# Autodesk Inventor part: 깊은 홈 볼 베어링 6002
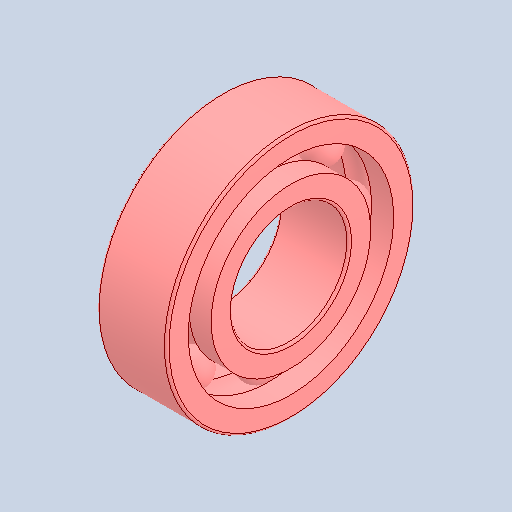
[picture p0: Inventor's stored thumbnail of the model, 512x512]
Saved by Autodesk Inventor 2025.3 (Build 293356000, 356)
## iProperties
Created: 2025-10
Part Number: 깊은 홈 볼 베어링 6002
Material: 강철, 연강
Description: 깊은 그루브 볼 베어링
Document SubType Name: Modeling
Designer: USER
Density: 7.85 g/cm^3
Appearance: 기본값
Author: jhkim
Sending System: Autodesk Inventor 2026
Preprocessor: ST-DEVELOPER v20.1
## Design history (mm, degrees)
feature "Solid1"
feature "Solid1:1"
feature "Solid1:2"
feature "Solid1:3"
feature "Solid1:4"
feature "Solid1:5"
feature "Solid1:6"
feature "Solid1:7"
feature "Solid1:8"
feature "Solid1:9"
node "솔리드1"
node "솔리드2"
node "솔리드3"
node "솔리드4"
node "솔리드5"
node "솔리드6"
node "솔리드7"
node "솔리드8"
node "솔리드9"
node "솔리드10"
